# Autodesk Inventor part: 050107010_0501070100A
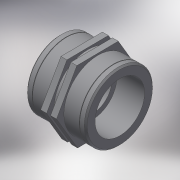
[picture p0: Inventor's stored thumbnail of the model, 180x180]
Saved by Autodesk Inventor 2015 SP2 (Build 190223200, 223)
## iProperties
Created: 2017-05
Part Number: 050107010_0501070100A
Material: Generic
Description: PLASSON SOCKET PP 1"-1"
Document SubType Name: Modeling
Designer: KIM
Density: 1 g/cm^3
Appearance: Default
Author: KIM
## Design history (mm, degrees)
derived "050107.ipt"
feature "Solid1::050107.ipt"
tag "TaggingFeature1"
body "Solid1"
other parameters: "d0" = 45, "d2" = 30.291, "d3" = 21, "d5" = 46, "d6" = 43.7, "d7" = 24.2328, "d14" = 0, "d15" = 0.90873, "d18" = 4.5, "d19" = 1.5, "d20" = 0.5, "d21" = 0.5, "d22" = 43.7, "Rp_" = 30.291, "H_" = 45, "l_2" = 21, "E_" = 46
